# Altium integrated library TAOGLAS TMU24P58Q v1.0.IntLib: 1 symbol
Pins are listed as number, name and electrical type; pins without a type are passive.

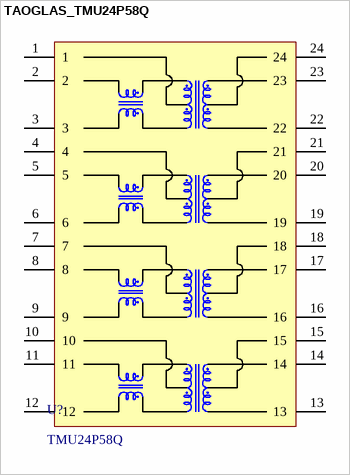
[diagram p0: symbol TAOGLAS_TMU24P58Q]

## TAOGLAS_TMU24P58Q
designator U?, comment TMU24P58Q
5G Base-T transformer Single Port and 24pin SMT; ComponentLibStatus: Created; MFG: Taoglas; Temp_High: +85C; Temp_Low: -40C
footprint TAOGLAS_TMU24P58Q (5G Base-T transformer Single Port and 24pin SMT)
pins: 1, 2, 3, 4, 5, 6, 7, 8, 9, 10, 11, 12, 13, 14, 15, 16, 17, 18, 19, 20, 21, 22, 23, 24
